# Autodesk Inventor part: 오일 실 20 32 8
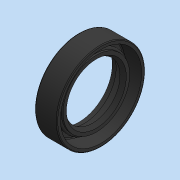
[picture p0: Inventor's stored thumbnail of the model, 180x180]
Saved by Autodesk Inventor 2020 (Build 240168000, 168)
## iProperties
Created: 2024-11
Part Number: 오일 실 20 32 8
Material: 고무
Description: 오일-실
Document SubType Name: Modeling
Designer: 1강의실14
Density: 0.93 g/cm^3
Appearance: 기본값
Author: jhkim
Sending System: Autodesk Inventor 2025
Preprocessor: ST-DEVELOPER v20
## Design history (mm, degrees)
node "오일 실 20 32 81"
node "솔리드1"
body "Solid1"
